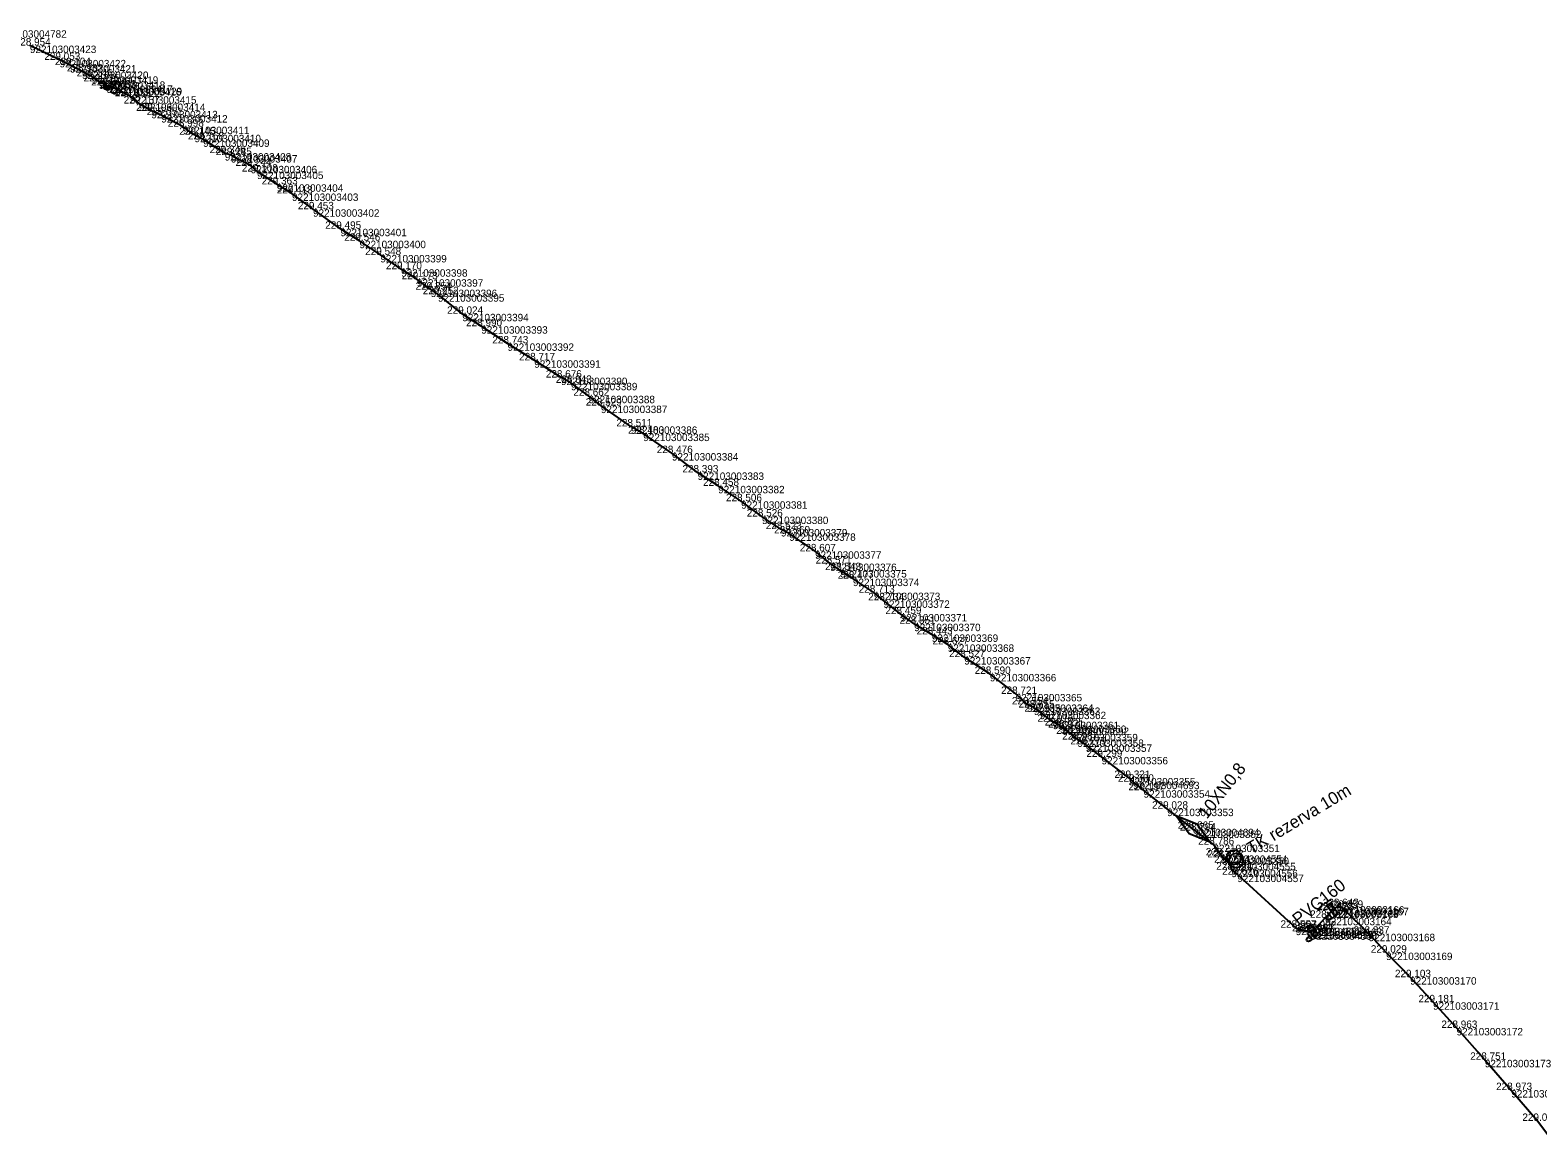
# Model space of a CAD drawing. Extents: x -771047 to -756200, y -1053876 to -1046520.
# Drawn here: x -769807.6 to -769564.4, y -1050333.1 to -1050153.5 of the extents above; entities that cross this region are included whole.
import ezdxf

# ---------------------------------------------------------------- set-up
doc = ezdxf.new("R2010")
doc.units = 0
for name, color, linetype in [('Vrstva 32', 7, 'Continuous'), ('Vrstva 33', 7, 'Continuous'), ('Vrstva 60', 7, 'Continuous'), ('Vrstva 61', 7, 'Continuous')]:
    doc.layers.add(name, color=color, linetype=linetype)

msp = doc.modelspace()

# ---------------------------------------------------------------- linework, layer by layer
at = {"layer": 'Vrstva 32'}
for points in [[(-769615.23, -1050286.93), (-769615.48, -1050286.61), (-769616.71, -1050284.87), (-769619.67, -1050282.59), (-769620.01, -1050282.31), (-769624.16, -1050279.07), (-769627.97, -1050276.09), (-769629.66, -1050274.72), (-769630.33, -1050274.11), (-769634.75, -1050270.72), (-769637.32, -1050268.7), (-769638.65, -1050267.91), (-769639.61, -1050267), (-769641.03, -1050265.99), (-769641.47, -1050265.65), (-769642.63, -1050265.04), (-769644.73, -1050263.42), (-769645.67, -1050262.75), (-769646.77, -1050262.26), (-769648.61, -1050260.56), (-769652.77, -1050257.33), (-769656.9, -1050254.62), (-769659.57, -1050252.57), (-769662.14, -1050250.96), (-769664.98, -1050249.23), (-769667.16, -1050247.67), (-769669.95, -1050245.47), (-769671.48, -1050244.22), (-769674.86, -1050241.96), (-769676.9, -1050240.58), (-769678.52, -1050239.53), (-769680.98, -1050237.55), (-769685.13, -1050234.66), (-769686.47, -1050233.96), (-769689.54, -1050231.95), (-769692.9, -1050229.48), (-769696.6, -1050226.99), (-769699.92, -1050224.83), (-769704.06, -1050221.71), (-769708.69, -1050218.57), (-769710.68, -1050217.4), (-769715.52, -1050214.05), (-769717.52, -1050212.46), (-769720.35, -1050210.38), (-769721.96, -1050209.53), (-769726.27, -1050206.74), (-769730.58, -1050204.01), (-769734.82, -1050201.24), (-769737.88, -1050199.24), (-769741.81, -1050196.08), (-769742.97, -1050195.34), (-769745.21, -1050193.66), (-769747.75, -1050192.05), (-769751.1, -1050189.75), (-769754.47, -1050187.45), (-769757.55, -1050185.52), (-769761.96, -1050182.38), (-769765.36, -1050179.83), (-769767.8, -1050178.35), (-769771, -1050176.3), (-769772.01, -1050175.37), (-769775.2, -1050173.64), (-769776.2, -1050173.32), (-769779.69, -1050171.11), (-769781.08, -1050170.36), (-769782.94, -1050169.05), (-769786.45, -1050167.18), (-769788.05, -1050166.5), (-769790.06, -1050165.32), (-769791.48, -1050164.14), (-769793.92, -1050162.86), (-769795.29, -1050162.4), (-769796.52, -1050161.75), (-769797.64, -1050160.94), (-769799.23, -1050160.15), (-769801.16, -1050159.12), (-769802.85, -1050158.28), (-769807.64, -1050155.97)], [(-769617.25, -1050284.47), (-769620.62, -1050283.1), (-769622.76, -1050280.16), (-769619.39, -1050281.52), (-769617.25, -1050284.47)], [(-769615.23, -1050286.93), (-769614.14, -1050287.79), (-769613.8, -1050288.91)], [(-769613.8, -1050288.91), (-769612.84, -1050289.71), (-769603.43, -1050298.27)], [(-769601.04, -1050299.02), (-769600.23, -1050298.38), (-769598.67, -1050296.67), (-769597.56, -1050295.49), (-769596.61, -1050294.78)], [(-769596.61, -1050294.78), (-769595.9, -1050295.06), (-769591.66, -1050299.24), (-769588.85, -1050302.29), (-769584.97, -1050306.25), (-769581.27, -1050310.3), (-769577.48, -1050314.44), (-769572.92, -1050319.58), (-769568.65, -1050324.46), (-769564.41, -1050329.43), (-769561.62, -1050333.13)], [(-769603.43, -1050298.27), (-769601.57, -1050298.87), (-769601.04, -1050299.02)]]:
    msp.add_lwpolyline(points, dxfattribs=at)
for centre in [(-769613.37, -1050286.91), (-769613.02, -1050287.44)]:
    msp.add_circle(centre, 1.17, dxfattribs=at)
at = {"layer": 'Vrstva 33'}
for points in [[(-769795.52, -1050162.99), (-769795.64, -1050162.87), (-769795.64, -1050162.64), (-769795.59, -1050162.54), (-769795.4, -1050162.41), (-769795.24, -1050162.44)], [(-769795.06, -1050163.23), (-769795.52, -1050162.99)], [(-769795.24, -1050162.44), (-769794.78, -1050162.68)], [(-769794.48, -1050162.12), (-769795.06, -1050163.23)], [(-769601.04, -1050299.02), (-769600.23, -1050298.38), (-769598.67, -1050296.67), (-769597.56, -1050295.49)], [(-769598.02, -1050297), (-769598.18, -1050297.05), (-769598.39, -1050296.95), (-769598.46, -1050296.86), (-769598.49, -1050296.63), (-769598.39, -1050296.5)], [(-769598.39, -1050296.5), (-769597.97, -1050296.19)], [(-769598.35, -1050295.68), (-769597.6, -1050296.68)], [(-769597.6, -1050296.68), (-769598.02, -1050297)], [(-769601.21, -1050300.46), (-769601.37, -1050300.51), (-769601.58, -1050300.42), (-769601.65, -1050300.34), (-769601.69, -1050300.11), (-769601.6, -1050299.97)], [(-769601.6, -1050299.97), (-769601.19, -1050299.65)], [(-769601.58, -1050299.15), (-769600.8, -1050300.13)], [(-769600.8, -1050300.13), (-769601.21, -1050300.46)]]:
    msp.add_lwpolyline(points, dxfattribs=at)
for points in [[(-769793.94, -1050163.81), (-769794.6, -1050163.47), (-769793.66, -1050161.68), (-769793, -1050162.03)], [(-769596.59, -1050295.92), (-769597.19, -1050296.37), (-769598.39, -1050294.75), (-769597.8, -1050294.31)], [(-769599.81, -1050299.34), (-769600.4, -1050299.81), (-769601.65, -1050298.23), (-769601.07, -1050297.76)]]:
    msp.add_lwpolyline(points, close=True, dxfattribs=at)
at = {"layer": 'Vrstva 60'}
for p, q in [((-769802.85, -1050158.28), (-769802.85, -1050158.28)), ((-769801.16, -1050159.12), (-769801.16, -1050159.12)), ((-769799.23, -1050160.15), (-769799.23, -1050160.15)), ((-769797.64, -1050160.94), (-769797.64, -1050160.94)), ((-769796.52, -1050161.75), (-769796.52, -1050161.75)), ((-769795.29, -1050162.4), (-769795.29, -1050162.4)), ((-769793.92, -1050162.86), (-769793.92, -1050162.86)), ((-769793.8, -1050162.75), (-769793.8, -1050162.75)), ((-769791.48, -1050164.14), (-769791.48, -1050164.14)), ((-769790.06, -1050165.32), (-769790.06, -1050165.32)), ((-769788.05, -1050166.5), (-769788.05, -1050166.5)), ((-769786.45, -1050167.18), (-769786.45, -1050167.18)), ((-769782.94, -1050169.05), (-769782.94, -1050169.05)), ((-769781.08, -1050170.36), (-769781.08, -1050170.36)), ((-769779.69, -1050171.11), (-769779.69, -1050171.11)), ((-769776.2, -1050173.32), (-769776.2, -1050173.32)), ((-769775.2, -1050173.64), (-769775.2, -1050173.64)), ((-769772.01, -1050175.37), (-769772.01, -1050175.37)), ((-769771, -1050176.3), (-769771, -1050176.3)), ((-769767.8, -1050178.35), (-769767.8, -1050178.35)), ((-769765.36, -1050179.83), (-769765.36, -1050179.83)), ((-769761.96, -1050182.38), (-769761.96, -1050182.38)), ((-769757.55, -1050185.52), (-769757.55, -1050185.52)), ((-769754.47, -1050187.45), (-769754.47, -1050187.45)), ((-769751.1, -1050189.75), (-769751.1, -1050189.75)), ((-769747.75, -1050192.05), (-769747.75, -1050192.05)), ((-769745.21, -1050193.66), (-769745.21, -1050193.66)), ((-769742.97, -1050195.34), (-769742.97, -1050195.34)), ((-769741.81, -1050196.08), (-769741.81, -1050196.08)), ((-769737.88, -1050199.24), (-769737.88, -1050199.24)), ((-769734.82, -1050201.24), (-769734.82, -1050201.24)), ((-769730.58, -1050204.01), (-769730.58, -1050204.01)), ((-769726.27, -1050206.74), (-769726.27, -1050206.74)), ((-769721.96, -1050209.53), (-769721.96, -1050209.53)), ((-769720.35, -1050210.38), (-769720.35, -1050210.38)), ((-769717.52, -1050212.46), (-769717.52, -1050212.46)), ((-769715.52, -1050214.05), (-769715.52, -1050214.05)), ((-769710.68, -1050217.4), (-769710.68, -1050217.4)), ((-769708.69, -1050218.57), (-769708.69, -1050218.57)), ((-769704.06, -1050221.71), (-769704.06, -1050221.71)), ((-769699.92, -1050224.83), (-769699.92, -1050224.83)), ((-769696.6, -1050226.99), (-769696.6, -1050226.99)), ((-769692.9, -1050229.48), (-769692.9, -1050229.48)), ((-769689.54, -1050231.95), (-769689.54, -1050231.95)), ((-769686.47, -1050233.96), (-769686.47, -1050233.96)), ((-769685.13, -1050234.66), (-769685.13, -1050234.66)), ((-769680.98, -1050237.55), (-769680.98, -1050237.55)), ((-769678.52, -1050239.53), (-769678.52, -1050239.53)), ((-769676.9, -1050240.58), (-769676.9, -1050240.58)), ((-769674.86, -1050241.96), (-769674.86, -1050241.96)), ((-769671.48, -1050244.22), (-769671.48, -1050244.22)), ((-769669.95, -1050245.47), (-769669.95, -1050245.47)), ((-769667.16, -1050247.67), (-769667.16, -1050247.67)), ((-769664.98, -1050249.23), (-769664.98, -1050249.23)), ((-769662.14, -1050250.96), (-769662.14, -1050250.96)), ((-769659.57, -1050252.57), (-769659.57, -1050252.57)), ((-769656.9, -1050254.62), (-769656.9, -1050254.62)), ((-769652.77, -1050257.33), (-769652.77, -1050257.33)), ((-769648.61, -1050260.56), (-769648.61, -1050260.56)), ((-769646.77, -1050262.26), (-769646.77, -1050262.26)), ((-769645.67, -1050262.75), (-769645.67, -1050262.75)), ((-769644.73, -1050263.42), (-769644.73, -1050263.42)), ((-769642.63, -1050265.04), (-769642.63, -1050265.04)), ((-769641.47, -1050265.65), (-769641.47, -1050265.65)), ((-769641.03, -1050265.99), (-769641.03, -1050265.99)), ((-769639.61, -1050267), (-769639.61, -1050267)), ((-769638.65, -1050267.91), (-769638.65, -1050267.91)), ((-769637.32, -1050268.7), (-769637.32, -1050268.7)), ((-769634.75, -1050270.72), (-769634.75, -1050270.72)), ((-769630.33, -1050274.11), (-769630.33, -1050274.11)), ((-769629.66, -1050274.72), (-769629.66, -1050274.72)), ((-769627.97, -1050276.09), (-769627.97, -1050276.09)), ((-769624.16, -1050279.07), (-769624.16, -1050279.07)), ((-769620.01, -1050282.31), (-769620.01, -1050282.31)), ((-769619.67, -1050282.59), (-769619.67, -1050282.59)), ((-769616.71, -1050284.87), (-769616.71, -1050284.87)), ((-769615.48, -1050286.61), (-769615.48, -1050286.61)), ((-769615.23, -1050286.93), (-769615.23, -1050286.93)), ((-769614.14, -1050287.79), (-769614.14, -1050287.79)), ((-769613.8, -1050288.91), (-769613.8, -1050288.91)), ((-769612.84, -1050289.71), (-769612.84, -1050289.71)), ((-769596.61, -1050294.78), (-769596.61, -1050294.78)), ((-769595.9, -1050295.06), (-769595.9, -1050295.06)), ((-769598.67, -1050296.67), (-769598.67, -1050296.67)), ((-769597.56, -1050295.49), (-769597.56, -1050295.49)), ((-769597.49, -1050295.34), (-769597.49, -1050295.34)), ((-769603.43, -1050298.27), (-769603.43, -1050298.27)), ((-769601.57, -1050298.87), (-769601.57, -1050298.87)), ((-769601.04, -1050299.02), (-769601.04, -1050299.02)), ((-769600.73, -1050298.78), (-769600.73, -1050298.78)), ((-769600.23, -1050298.38), (-769600.23, -1050298.38)), ((-769591.66, -1050299.24), (-769591.66, -1050299.24)), ((-769588.85, -1050302.29), (-769588.85, -1050302.29)), ((-769584.97, -1050306.25), (-769584.97, -1050306.25)), ((-769581.27, -1050310.3), (-769581.27, -1050310.3)), ((-769577.48, -1050314.44), (-769577.48, -1050314.44)), ((-769572.92, -1050319.58), (-769572.92, -1050319.58)), ((-769568.65, -1050324.46), (-769568.65, -1050324.46)), ((-769564.41, -1050329.43), (-769564.41, -1050329.43))]:
    msp.add_line(p, q, dxfattribs=at)

# ---------------------------------------------------------------- texts
at = {"layer": 'Vrstva 32'}
for s, rotation, p in [('10XN0,8', 52.0144, (-769617.76, -1050280.84)), ('TK rezerva 10m', 31.1852, (-769610.56, -1050286.51))]:
    msp.add_text(s, height=2, rotation=rotation, dxfattribs=at).set_placement(p)
at = {"layer": 'Vrstva 33'}
msp.add_text('PVC160', height=2, rotation=38.4166, dxfattribs=at).set_placement((-769602.99, -1050297.98))
at = {"layer": 'Vrstva 60'}
for s, p in [('922103004782', (-769812.42, -1050154.7)), ('922103003423', (-769807.64, -1050157.17)), ('922103003422', (-769802.85, -1050159.48)), ('922103003421', (-769801.16, -1050160.32)), ('922103003420', (-769799.23, -1050161.35)), ('922103003419', (-769797.64, -1050162.14)), ('922103003418', (-769796.52, -1050162.95)), ('922103003417', (-769795.29, -1050163.6)), ('922103003416', (-769793.92, -1050164.06)), ('922103005129', (-769793.8, -1050163.95)), ('922103003415', (-769791.48, -1050165.34)), ('922103003414', (-769790.06, -1050166.52)), ('922103003413', (-769788.05, -1050167.7)), ('922103003412', (-769786.45, -1050168.38)), ('922103003411', (-769782.94, -1050170.25)), ('922103003410', (-769781.08, -1050171.56)), ('922103003409', (-769779.69, -1050172.31)), ('922103003408', (-769776.2, -1050174.52)), ('922103003407', (-769775.2, -1050174.84)), ('922103003406', (-769772.01, -1050176.57)), ('922103003405', (-769771, -1050177.5)), ('922103003404', (-769767.8, -1050179.55)), ('922103003403', (-769765.36, -1050181.03)), ('922103003402', (-769761.96, -1050183.58)), ('922103003401', (-769757.55, -1050186.72)), ('922103003400', (-769754.47, -1050188.65)), ('922103003399', (-769751.1, -1050190.95)), ('922103003398', (-769747.75, -1050193.25)), ('922103003397', (-769745.21, -1050194.86)), ('922103003396', (-769742.97, -1050196.54)), ('922103003395', (-769741.81, -1050197.28)), ('922103003394', (-769737.88, -1050200.44)), ('922103003393', (-769734.82, -1050202.44)), ('922103003392', (-769730.58, -1050205.21)), ('922103003391', (-769726.27, -1050207.94)), ('922103003390', (-769721.96, -1050210.73)), ('922103003389', (-769720.35, -1050211.57)), ('922103003388', (-769717.52, -1050213.66)), ('922103003387', (-769715.52, -1050215.25)), ('922103003386', (-769710.68, -1050218.6)), ('922103003385', (-769708.69, -1050219.77)), ('922103003384', (-769704.06, -1050222.91)), ('922103003383', (-769699.92, -1050226.03)), ('922103003382', (-769696.6, -1050228.19)), ('922103003381', (-769692.9, -1050230.68)), ('922103003380', (-769689.54, -1050233.15)), ('922103003379', (-769686.47, -1050235.16)), ('922103003378', (-769685.13, -1050235.86)), ('922103003377', (-769680.98, -1050238.75)), ('922103003376', (-769678.52, -1050240.73)), ('922103003375', (-769676.9, -1050241.78)), ('922103003374', (-769674.86, -1050243.16)), ('922103003373', (-769671.48, -1050245.42)), ('922103003372', (-769669.95, -1050246.67)), ('922103003371', (-769667.16, -1050248.87)), ('922103003370', (-769664.98, -1050250.43)), ('922103003369', (-769662.14, -1050252.16)), ('922103003368', (-769659.57, -1050253.77)), ('922103003367', (-769656.9, -1050255.82)), ('922103003366', (-769652.77, -1050258.53)), ('922103003365', (-769648.61, -1050261.76)), ('922103003364', (-769646.77, -1050263.46)), ('922103003363', (-769645.67, -1050263.95)), ('922103003362', (-769644.73, -1050264.62)), ('922103003361', (-769642.63, -1050266.24)), ('922103003360', (-769641.47, -1050266.85)), ('922103004692', (-769641.03, -1050267.19)), ('922103003359', (-769639.61, -1050268.2)), ('922103003358', (-769638.65, -1050269.11)), ('922103003357', (-769637.32, -1050269.9)), ('922103003356', (-769634.75, -1050271.92)), ('922103003355', (-769630.33, -1050275.31)), ('922103004693', (-769629.66, -1050275.92)), ('922103003354', (-769627.97, -1050277.29)), ('922103003353', (-769624.16, -1050280.27)), ('922103004694', (-769620.01, -1050283.51)), ('922103003352', (-769619.67, -1050283.79)), ('922103003351', (-769616.71, -1050286.07)), ('922103004554', (-769615.48, -1050287.81)), ('922103003350', (-769615.23, -1050288.13)), ('922103004555', (-769614.14, -1050288.99)), ('922103004556', (-769613.8, -1050290.11)), ('922103004557', (-769612.84, -1050290.91)), ('922103003166', (-769596.61, -1050295.98)), ('922103003167', (-769595.9, -1050296.26)), ('922103003164', (-769598.67, -1050297.87)), ('922103003165', (-769597.56, -1050296.69)), ('922103005128', (-769597.49, -1050296.54)), ('922103004558', (-769603.43, -1050299.47)), ('922103004559', (-769601.57, -1050300.07)), ('922103004560', (-769601.04, -1050300.22)), ('922103005127', (-769600.73, -1050299.98)), ('922103003163', (-769600.23, -1050299.58)), ('922103003168', (-769591.66, -1050300.44)), ('922103003169', (-769588.85, -1050303.49)), ('922103003170', (-769584.97, -1050307.45)), ('922103003171', (-769581.27, -1050311.5)), ('922103003172', (-769577.48, -1050315.64)), ('922103003173', (-769572.92, -1050320.78)), ('922103003174', (-769568.65, -1050325.66))]:
    msp.add_text(s, height=1.2, dxfattribs=at).set_placement(p)
at = {"layer": 'Vrstva 61'}
for s, p in [('228.954', (-769810.09, -1050155.97)), ('229.053', (-769805.31, -1050158.28)), ('229.104', (-769803.61, -1050159.12)), ('228.932', (-769801.68, -1050160.15)), ('229.146', (-769800.09, -1050160.94)), ('229.225', (-769798.97, -1050161.75)), ('229.234', (-769797.74, -1050162.4)), ('229.083', (-769796.37, -1050162.86)), ('229.633', (-769796.25, -1050162.75)), ('229.122', (-769793.93, -1050164.14)), ('229.157', (-769792.51, -1050165.32)), ('229.196', (-769790.5, -1050166.5)), ('229.051', (-769788.8, -1050167.18)), ('228.998', (-769785.39, -1050169.05)), ('229.145', (-769783.54, -1050170.36)), ('229.168', (-769782.14, -1050171.11)), ('229.346', (-769778.65, -1050173.32)), ('229.285', (-769777.65, -1050173.64)), ('229.244', (-769774.46, -1050175.37)), ('229.108', (-769773.45, -1050176.3)), ('229.363', (-769770.25, -1050178.35)), ('229.413', (-769767.82, -1050179.83)), ('229.453', (-769764.41, -1050182.38)), ('229.495', (-769760, -1050185.52)), ('229.546', (-769756.92, -1050187.45)), ('229.548', (-769753.55, -1050189.75)), ('229.170', (-769750.2, -1050192.05)), ('229.173', (-769747.66, -1050193.66)), ('229.354', (-769745.42, -1050195.34)), ('229.252', (-769744.26, -1050196.08)), ('229.024', (-769740.33, -1050199.24)), ('228.990', (-769737.27, -1050201.24)), ('228.743', (-769733.04, -1050204.01)), ('228.717', (-769728.72, -1050206.74)), ('228.676', (-769724.41, -1050209.53)), ('228.843', (-769722.8, -1050210.38)), ('228.662', (-769719.97, -1050212.46)), ('228.529', (-769717.97, -1050214.05)), ('228.511', (-769713.03, -1050217.4)), ('228.480', (-769711.14, -1050218.57)), ('228.476', (-769706.51, -1050221.71)), ('228.393', (-769702.37, -1050224.83)), ('228.458', (-769699.05, -1050226.99)), ('228.506', (-769695.35, -1050229.48)), ('228.526', (-769691.99, -1050231.95)), ('228.523', (-769688.92, -1050233.96)), ('228.560', (-769687.58, -1050234.66)), ('228.607', (-769683.43, -1050237.55)), ('228.571', (-769680.88, -1050239.53)), ('228.543', (-769679.35, -1050240.58)), ('228.477', (-769677.31, -1050241.96)), ('228.713', (-769673.93, -1050244.22)), ('228.734', (-769672.4, -1050245.47)), ('228.459', (-769669.62, -1050247.67)), ('228.351', (-769667.34, -1050249.23)), ('228.443', (-769664.59, -1050250.96)), ('228.627', (-769662.02, -1050252.57)), ('228.527', (-769659.35, -1050254.62)), ('228.590', (-769655.22, -1050257.33)), ('228.721', (-769650.97, -1050260.56)), ('228.554', (-769649.22, -1050262.26)), ('228.655', (-769648.13, -1050262.75)), ('228.935', (-769647.18, -1050263.42)), ('229.015', (-769645.09, -1050265.04)), ('229.022', (-769643.92, -1050265.65)), ('228.971', (-769643.39, -1050265.99)), ('228.989', (-769642.07, -1050267)), ('228.987', (-769641.1, -1050267.91)), ('229.279', (-769639.78, -1050268.7)), ('229.299', (-769637.2, -1050270.72)), ('229.321', (-769632.68, -1050274.11)), ('229.380', (-769632.11, -1050274.72)), ('229.197', (-769630.42, -1050276.09)), ('229.028', (-769626.61, -1050279.07)), ('228.865', (-769622.46, -1050282.31)), ('228.794', (-769622.12, -1050282.59)), ('228.786', (-769619.16, -1050284.87)), ('228.572', (-769617.93, -1050286.61)), ('228.403', (-769617.68, -1050286.93)), ('228.604', (-769616.59, -1050287.79)), ('228.494', (-769616.25, -1050288.91)), ('228.626', (-769615.29, -1050289.71)), ('228.672', (-769600.01, -1050295.49)), ('229.428', (-769599.95, -1050295.34)), ('228.643', (-769599.06, -1050294.78)), ('228.859', (-769598.35, -1050295.06)), ('228.557', (-769605.88, -1050298.27)), ('228.745', (-769604.03, -1050298.87)), ('229.644', (-769603.18, -1050298.78)), ('227.992', (-769602.68, -1050298.38)), ('228.092', (-769601.11, -1050296.67)), ('228.686', (-769603.49, -1050299.02)), ('228.837', (-769594.11, -1050299.24)), ('229.029', (-769591.31, -1050302.29)), ('229.103', (-769587.42, -1050306.25)), ('229.181', (-769583.63, -1050310.3)), ('228.963', (-769579.93, -1050314.44)), ('228.751', (-769575.28, -1050319.58)), ('228.973', (-769571.1, -1050324.46)), ('229.098', (-769566.86, -1050329.43))]:
    msp.add_text(s, height=1.2, dxfattribs=at).set_placement(p)

doc.saveas('drawing.dxf')
